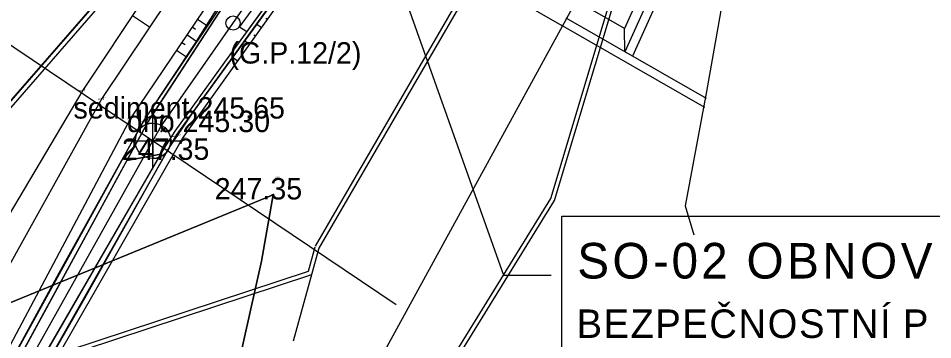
# Model space of a CAD drawing. Extents: x -555757 to -553364, y -1100723 to -1096439.
# Drawn here: x -554242.8 to -554178.6, y -1096874.8 to -1096852.2 of the extents above; entities that cross this region are included whole.
import ezdxf

# ---------------------------------------------------------------- set-up
doc = ezdxf.new("R2010")
doc.units = 0
for name, color, linetype in [('00_NÁVRH - 0.18 mm', 7, 'Continuous'), ('00_NÁVRH - 0.35 mm', 7, 'Continuous'), ('00_NÁVRH - 0.50 mm', 7, 'Continuous'), ('00_NÁVRH - Kóty výškové', 7, 'Continuous'), ('00_NÁVRH - Popis', 7, 'Continuous'), ('00_NÁVRH - Řezy', 7, 'Continuous'), ('01_HLADINA', 7, 'Continuous'), ('Geodet. výšky - netisknuté', 7, 'Continuous'), ('HRANA$SVAHU', 7, 'Continuous'), ('HRANICE$PARCELY', 7, 'Continuous'), ('NÁVRH', 7, 'Continuous'), ('OSA$KOLEJI', 7, 'Continuous'), ('POPIS', 7, 'Continuous'), ('ROZHRANI', 7, 'Continuous'), ('VYSKA_PODR_BOD', 7, 'Continuous'), ('VYSKOVE$SRAFY', 7, 'Continuous'), ('zájem', 7, 'Continuous')]:
    doc.layers.add(name, color=color, linetype=linetype)

# ---------------------------------------------------------------- blocks, each defined once
blk = doc.blocks.new('POINT_DISPLAY')
blk.add_line((0, 0), (0, 0))
blk = doc.blocks.new('BOD')
at = {"layer": 'POPIS'}
for p, q in [((-0.283, -0.283), (0.283, 0.283)), ((-0.283, 0.283), (0.283, -0.283))]:
    blk.add_line(p, q, dxfattribs=at)
blk = doc.blocks.new('ZN_Výšková kóta - Půdorys')
for p, q in [((0, -2), (0, 2)), ((-2, 0), (2, 0))]:
    blk.add_line(p, q)
for points in [[(-1.25, 0), (0, 0), (0, 1.25)], [(1.25, 0), (0, 0), (0, -1.25)]]:
    blk.add_lwpolyline(points)
blk.add_circle((0, 0), 1.25)
for start, end in [(90, 180), (270, 0)]:
    blk.add_arc((0, 0), 1.25, start, end)

msp = doc.modelspace()

# ---------------------------------------------------------------- linework, layer by layer
for points in [[(-554217.186, -1096846.488), (-554208.76, -1096870.255)], [(-554208.76, -1096870.255), (-554205.417, -1096870.255)]]:
    msp.add_lwpolyline(points)
at = {"layer": '00_NÁVRH - 0.18 mm'}
for points in [[(-554244.222, -1096877.946), (-554239.928, -1096870.081), (-554234.389, -1096860.12), (-554233.805, -1096859.133), (-554230.381, -1096853.989), (-554224.046, -1096843.91), (-554222.437, -1096841.751), (-554216.84, -1096834.596), (-554215.638, -1096833.106), (-554214.628, -1096832.253), (-554213.878, -1096831.54), (-554208.044, -1096827.257), (-554206.604, -1096826.656), (-554199.585, -1096824.093), (-554195.86, -1096822.69), (-554194.845, -1096822.577), (-554193.89, -1096822.47)], [(-554257.674, -1096913.609), (-554257.386, -1096904.184), (-554257.334, -1096903.927), (-554257.244, -1096903.68), (-554253.91, -1096896.5), (-554246.263, -1096883.55), (-554242.882, -1096877.885), (-554232.814, -1096859.873), (-554221.954, -1096844.276), (-554214.583, -1096834.434), (-554207.357, -1096828.39), (-554204.597, -1096827.342), (-554200.893, -1096825.981), (-554199.43, -1096825.685), (-554196.267, -1096825.045), (-554193.7, -1096825.229), (-554189.701, -1096825.925)], [(-554256.602, -1096912.935), (-554256.472, -1096905.789), (-554256.409, -1096904.621), (-554256.316, -1096904.033), (-554256.192, -1096903.62), (-554254.599, -1096900.381), (-554252.831, -1096896.798), (-554252.356, -1096895.943), (-554242.247, -1096879.075), (-554238.131, -1096871.857), (-554232.321, -1096861.512), (-554230.576, -1096858.893), (-554220.275, -1096844.692), (-554215.749, -1096838.882), (-554212.975, -1096835.911), (-554211.13, -1096834.122), (-554207.196, -1096830.262), (-554206.098, -1096829.593), (-554204.263, -1096829.043), (-554200.835, -1096828.054), (-554199.681, -1096827.841), (-554198.092, -1096827.737), (-554194.79, -1096827.55)]]:
    msp.add_lwpolyline(points, dxfattribs=at)
at = {"layer": '00_NÁVRH - 0.35 mm'}
msp.add_line((-554226.767, -1096853.181), (-554227.271, -1096852.853), dxfattribs=at)
for points in [[(-554258.424, -1096913.609), (-554258.136, -1096904.184), (-554258.084, -1096903.927), (-554257.994, -1096903.657), (-554254.805, -1096896.5), (-554254.006, -1096895.143), (-554247.013, -1096883.55), (-554243.71, -1096877.885), (-554234.133, -1096860.293), (-554233.564, -1096859.274), (-554223.04, -1096843.11), (-554215.394, -1096833.291), (-554213.531, -1096831.866), (-554207.751, -1096827.646), (-554205.603, -1096826.85), (-554202.523, -1096825.678), (-554200.576, -1096824.944), (-554197.017, -1096823.505), (-554194.826, -1096822.911)], [(-554227.271, -1096852.853), (-554220.77, -1096843.92), (-554214.025, -1096834.914), (-554212.083, -1096833.16), (-554207.18, -1096828.732), (-554200.791, -1096826.871), (-554198.983, -1096826.587)], [(-554256.924, -1096913.609), (-554256.636, -1096904.184), (-554256.584, -1096903.927), (-554256.474, -1096903.627), (-554253.291, -1096896.909), (-554252.611, -1096895.819), (-554245.513, -1096883.55), (-554242.132, -1096877.928), (-554232.557, -1096861.353), (-554231.794, -1096860.142), (-554228.306, -1096855.295), (-554220.288, -1096844.276), (-554213.58, -1096835.32), (-554211.681, -1096833.605), (-554206.88, -1096829.27), (-554200.66, -1096827.458), (-554198.89, -1096827.18)]]:
    msp.add_lwpolyline(points, dxfattribs=at)
at = {"layer": '00_NÁVRH - 0.50 mm'}
msp.add_circle((-554227.722, -1096852.559), 0.5, dxfattribs=at)
at = {"layer": '00_NÁVRH - Popis'}
msp.add_lwpolyline([(-554204.667, -1096866.109), (-554156.972, -1096866.109), (-554156.972, -1096876.306), (-554204.667, -1096876.306)], close=True, dxfattribs=at)
at = {"layer": '00_NÁVRH - Řezy'}
msp.add_line((-554250.686, -1096849.155), (-554216.283, -1096872.303), dxfattribs=at)
at = {"layer": '01_HLADINA'}
for p, q in [((-554197.513, -1096839.721), (-554221.584, -1096883.775)), ((-554223.04, -1096843.11), (-554233.564, -1096859.274)), ((-554228.306, -1096855.295), (-554220.288, -1096844.276)), ((-554231.794, -1096860.142), (-554228.306, -1096855.295)), ((-554233.564, -1096859.274), (-554234.133, -1096860.293)), ((-554234.133, -1096860.293), (-554235.18, -1096862.215)), ((-554232.557, -1096861.353), (-554231.794, -1096860.142)), ((-554232.786, -1096861.75), (-554232.557, -1096861.353)), ((-554235.18, -1096862.215), (-554243.71, -1096877.885)), ((-554242.132, -1096877.928), (-554232.786, -1096861.75)), ((-554232.786, -1096861.75), (-554235.18, -1096862.215)), ((-554235.18, -1096862.215), (-554232.786, -1096861.75))]:
    msp.add_line(p, q, dxfattribs=at)
at = {"layer": 'HRANA$SVAHU'}
for p, q in [((-554227.2, -1096840.64), (-554238.26, -1096857.26)), ((-554225.72, -1096841.04), (-554236.92, -1096857.85)), ((-554223.97, -1096842.99), (-554234.89, -1096859.22)), ((-554223.04, -1096843.11), (-554234.01, -1096859.43)), ((-554231.72, -1096860.45), (-554220.69, -1096845.18)), ((-554231.27, -1096860.66), (-554220.21, -1096845.16)), ((-554238.26, -1096857.26), (-554247.85, -1096873.44)), ((-554236.92, -1096857.85), (-554246.22, -1096874.57)), ((-554234.89, -1096859.22), (-554244.18, -1096876.7)), ((-554234.01, -1096859.43), (-554243.79, -1096877.22)), ((-554242.22, -1096878.99), (-554231.72, -1096860.45)), ((-554242, -1096879.4), (-554231.27, -1096860.66))]:
    msp.add_line(p, q, dxfattribs=at)
at = {"layer": 'HRANICE$PARCELY'}
for p, q in [((-554202.71, -1096835.61), (-554221.7, -1096868.36)), ((-554205.44, -1096864.88), (-554198.46, -1096841.64)), ((-554212.08, -1096875.63), (-554205.44, -1096864.88)), ((-554221.7, -1096868.36), (-554223.51, -1096874.88)), ((-554222.22, -1096870.23), (-554243.68, -1096877.3))]:
    msp.add_line(p, q, dxfattribs=at)
at = {"layer": 'NÁVRH'}
for points in [[(-554197.122, -1096845.979), (-554200.264, -1096852.938)], [(-554196.512, -1096846.329), (-554200.232, -1096854.57)], [(-554195.989, -1096846.629), (-554199.709, -1096854.87)], [(-554212.457, -1096848.247), (-554204.651, -1096852.727)], [(-554193.251, -1096850.206), (-554194.511, -1096857.355), (-554196.005, -1096865.395), (-554195.389, -1096867.414)], [(-554200.264, -1096852.938), (-554203.655, -1096850.992)], [(-554194.625, -1096858.479), (-554204.651, -1096852.727)], [(-554194.515, -1096857.851), (-554204.352, -1096852.206)], [(-554200.232, -1096854.57), (-554200.264, -1096852.938)]]:
    msp.add_lwpolyline(points, dxfattribs=at)
at = {"layer": 'OSA$KOLEJI'}
msp.add_line((-554235.49, -1096849.02), (-554251.92, -1096867.91), dxfattribs=at)
msp.add_line((-554235.49, -1096849.02), (-554251.92, -1096867.91), dxfattribs=at)
at = {"layer": 'POPIS'}
for p, q in [((-554203.007, -1096835.524), (-554221.96, -1096868.21)), ((-554205.165, -1096865.005), (-554198.189, -1096841.78)), ((-554235.264, -1096849.217), (-554251.694, -1096868.107)), ((-554211.796, -1096875.741), (-554205.165, -1096865.005)), ((-554221.989, -1096868.28), (-554222.465, -1096869.995)), ((-554222.465, -1096869.995), (-554243.849, -1096877.04))]:
    msp.add_line(p, q, dxfattribs=at)
at = {"layer": 'VYSKOVE$SRAFY'}
for p, q in [((-554233.583, -1096852.842), (-554234.786, -1096852.04)), ((-554230.225, -1096852.287), (-554229.526, -1096852.758)), ((-554225.73, -1096852.897), (-554226.083, -1096852.645)), ((-554225.314, -1096852.313), (-554225.43, -1096852.23)), ((-554230.954, -1096853.37), (-554230.253, -1096853.841)), ((-554230.589, -1096852.828), (-554230.356, -1096852.986)), ((-554226.147, -1096853.481), (-554226.266, -1096853.396)), ((-554231.318, -1096853.911), (-554231.084, -1096854.068)), ((-554226.564, -1096854.064), (-554226.923, -1096853.808)), ((-554231.682, -1096854.453), (-554230.982, -1096854.925)), ((-554226.98, -1096854.648), (-554227.101, -1096854.562)), ((-554227.397, -1096855.232), (-554227.762, -1096854.971))]:
    msp.add_line(p, q, dxfattribs=at)
at = {"layer": 'zájem'}
for points in [[(-554110.69, -1096747.36), (-554142.08, -1096773.53), (-554179.17, -1096807.62), (-554205.78, -1096822.41), (-554208.2, -1096823.7), (-554225.08, -1096837.14), (-554235.5, -1096849), (-554251.97, -1096867.91), (-554264.55, -1096882.42), (-554265.7, -1096883.76), (-554272.88, -1096891.67), (-554281.79, -1096901.5), (-554289.93, -1096910.44), (-554329.92, -1096954.43), (-554333.96, -1096958.92), (-554536.43, -1097182.04), (-554585.15, -1097235.78), (-554588.14, -1097239.01), (-554733.55, -1097399.26)], [(-554733.55, -1097399.26), (-554588.14, -1097239.01), (-554585.15, -1097235.78), (-554536.43, -1097182.04), (-554333.96, -1096958.92), (-554329.92, -1096954.43), (-554289.93, -1096910.44), (-554281.79, -1096901.5), (-554272.88, -1096891.67), (-554265.7, -1096883.76), (-554264.55, -1096882.42), (-554251.97, -1096867.91), (-554235.5, -1096849), (-554225.08, -1096837.14), (-554208.2, -1096823.7), (-554205.78, -1096822.41), (-554179.17, -1096807.62), (-554142.08, -1096773.53), (-554110.69, -1096747.36)], [(-554190.63, -1097034.96), (-554197.16, -1097028.05), (-554217.46, -1096987.98), (-554225.33, -1096977.64), (-554234.21, -1096944.26), (-554236.99, -1096909.92), (-554235.22, -1096898.62), (-554228.6, -1096882.13), (-554225.73, -1096869.26), (-554224.9, -1096864.61), (-554233.29, -1096868.06), (-554243.42, -1096872.22), (-554247.48, -1096879.5), (-554255.66, -1096892.57), (-554260.45, -1096913.44), (-554248.68, -1096931.61), (-554247, -1096951.09), (-554248.74, -1096969.23), (-554247.82, -1097012.49), (-554234.69, -1097042.48)], [(-554234.69, -1097042.48), (-554247.82, -1097012.49), (-554248.74, -1096969.23), (-554247, -1096951.09), (-554248.68, -1096931.61), (-554260.45, -1096913.44), (-554255.66, -1096892.57), (-554247.48, -1096879.5), (-554243.42, -1096872.22), (-554233.29, -1096868.06), (-554224.9, -1096864.61), (-554225.73, -1096869.26), (-554228.6, -1096882.13), (-554235.22, -1096898.62), (-554236.99, -1096909.92), (-554234.21, -1096944.26), (-554225.33, -1096977.64), (-554217.46, -1096987.98), (-554197.16, -1097028.05), (-554190.63, -1097034.96)]]:
    msp.add_lwpolyline(points, dxfattribs=at)

# ---------------------------------------------------------------- block references
at = {"layer": '00_NÁVRH - Kóty výškové'}
msp.add_blockref('ZN_Výšková kóta - Půdorys', (-554233.345, -1096860.823), dxfattribs=at)
at = {"layer": 'POPIS', "xscale": 0.5624965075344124, "yscale": 0.5624965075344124}
for p in [(-554232.63, -1096860.02), (-554232.63, -1096860.06)]:
    msp.add_blockref('BOD', p, dxfattribs=at)
at = {"layer": 'ROZHRANI'}
for p in [(-554238.26, -1096857.26), (-554236.92, -1096857.85), (-554234.89, -1096859.22), (-554234.01, -1096859.43), (-554232.63, -1096860.02), (-554232.63, -1096860.06), (-554231.72, -1096860.45), (-554231.27, -1096860.66), (-554224.76, -1096863.44)]:
    msp.add_blockref('POINT_DISPLAY', p, dxfattribs=at)

# ---------------------------------------------------------------- texts
at = {"layer": '00_NÁVRH - Popis'}
for s, height, p in [('S', 2.5, (-554203.574, -1096870.489)), ('O', 2.5, (-554201.111, -1096870.489)), ('0', 2.5, (-554196.963, -1096870.489)), ('2', 2.5, (-554194.886, -1096870.489)), ('O', 2.5, (-554191.705, -1096870.489)), ('B', 2.5, (-554188.855, -1096870.489)), ('N', 2.5, (-554186.391, -1096870.489)), ('O', 2.5, (-554183.735, -1096870.489)), ('V', 2.5, (-554180.884, -1096870.489)), ('-', 2.5, (-554198.26, -1096870.489)), ('Č', 2, (-554194.314, -1096874.66)), ('O', 2, (-554190.22, -1096874.66)), ('S', 2, (-554188.017, -1096874.66)), ('Í', 2, (-554182.341, -1096874.66)), ('B', 2, (-554203.622, -1096874.66)), ('E', 2, (-554201.729, -1096874.66)), ('Z', 2, (-554199.836, -1096874.66)), ('P', 2, (-554198.1, -1096874.66)), ('E', 2, (-554196.207, -1096874.66)), ('N', 2, (-554192.267, -1096874.66)), ('T', 2, (-554186.124, -1096874.66)), ('N', 2, (-554184.388, -1096874.66)), ('P', 2, (-554180.729, -1096874.66))]:
    msp.add_text(s, height=height, dxfattribs=at).set_placement(p)
at = {"layer": 'Geodet. výšky - netisknuté'}
for s, p in [('247.11', (-554238.535, -1096857.36)), ('247.71', (-554237.195, -1096857.95)), ('246.75', (-554235.173, -1096859.32)), ('245.85', (-554234.293, -1096859.53)), ('245.65', (-554232.913, -1096860.12)), ('245.30', (-554232.913, -1096860.16)), ('245.85', (-554232.003, -1096860.55))]:
    msp.add_text(s, height=0.1, dxfattribs=at).set_placement(p)
at = {"layer": 'OSA$KOLEJI'}
for s, p in [('2313', (-554238.26, -1096857.26)), ('2314', (-554236.92, -1096857.85)), ('2315', (-554234.89, -1096859.22)), ('2316', (-554234.01, -1096859.43)), ('2317', (-554232.63, -1096860.02)), ('2318', (-554232.63, -1096860.06)), ('2319', (-554231.72, -1096860.45)), ('2320', (-554231.27, -1096860.66)), ('2321', (-554224.76, -1096863.44))]:
    msp.add_text(s, height=0.1, dxfattribs=at).set_placement(p)
at = {"layer": 'POPIS'}
for s, p in [('(G.P.12/2)', (-554227.97, -1096855.4)), ('sediment 245.65', (-554238.916, -1096859.261)), ('dno 245.30', (-554235.166, -1096860.211))]:
    msp.add_text(s, height=1.5, dxfattribs=at).set_placement(p)
at = {"layer": 'VYSKA_PODR_BOD'}
for p in [(-554235.52, -1096862.16), (-554229.01, -1096864.94)]:
    msp.add_text('247.35', height=1.5, dxfattribs=at).set_placement(p)

doc.saveas('drawing.dxf')
